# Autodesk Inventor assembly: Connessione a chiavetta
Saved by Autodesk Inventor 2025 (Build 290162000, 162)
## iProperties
Created: 2026-05
Part Number: Connessione a chiavetta
Document SubType Name: Assembly
Designer: Ryzen5700u
ClientObjectVersion: 1
Author: Ryzen5700u
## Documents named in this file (1)
- C:\Users\Ryzen5700u\Desktop\riduttore pompa\riduttore2\Design Accelerator\Connessione a chiavetta3.iam
